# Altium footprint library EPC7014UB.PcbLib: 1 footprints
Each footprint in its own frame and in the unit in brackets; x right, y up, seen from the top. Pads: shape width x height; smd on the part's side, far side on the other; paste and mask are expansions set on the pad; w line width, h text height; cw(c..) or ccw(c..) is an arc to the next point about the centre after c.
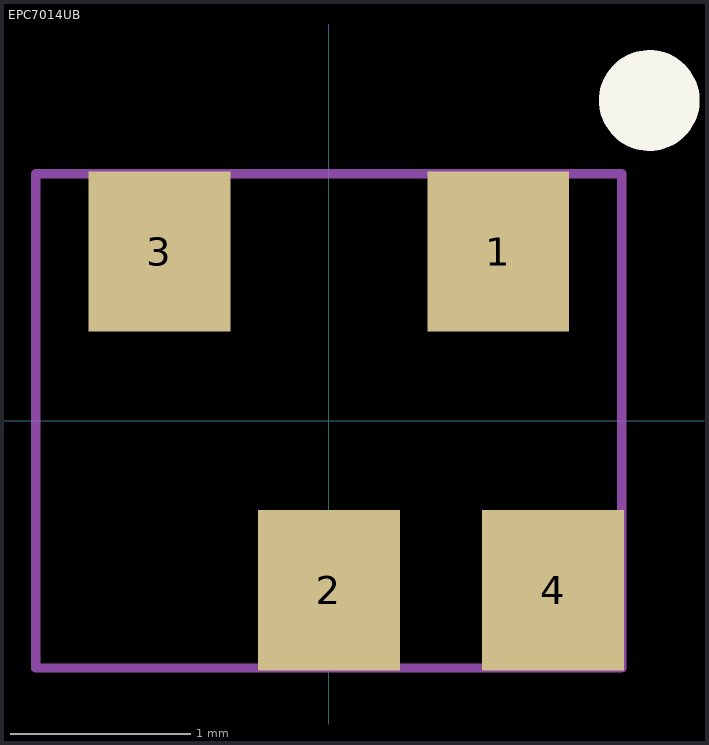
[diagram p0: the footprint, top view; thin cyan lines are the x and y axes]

## EPC7014UB [mil] "UB package Footprint used for surface mounting devices"
pads (4):
  rect 31x35 smd paste+3 mask+3: 1(37,37) 2(0,-37) 3(-37,37) 4(49,-37)
Top Overlay:
  circle w12: c70,70 r5
Mechanical 1:
  lines w2: -64,-54 64,-54 64,54 -64,54 -64,-54
Mechanical 2:
  text "S" at -82.66,28 h20
  text "D" at -45.66,-48 h20
  text "L" at 96.34,-47 h20
  text "G" at 69.34,26 h20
